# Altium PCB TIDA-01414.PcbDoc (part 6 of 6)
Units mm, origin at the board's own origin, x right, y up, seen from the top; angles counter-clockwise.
Board outline 400 x 135 mm, 4 copper layers (Top Copper, Copper Layer 2, Copper Layer 3, Bottom Copper), stack 1.567 mm thick; 835 components, 519 nets, 2420 pads, 2045 vias.
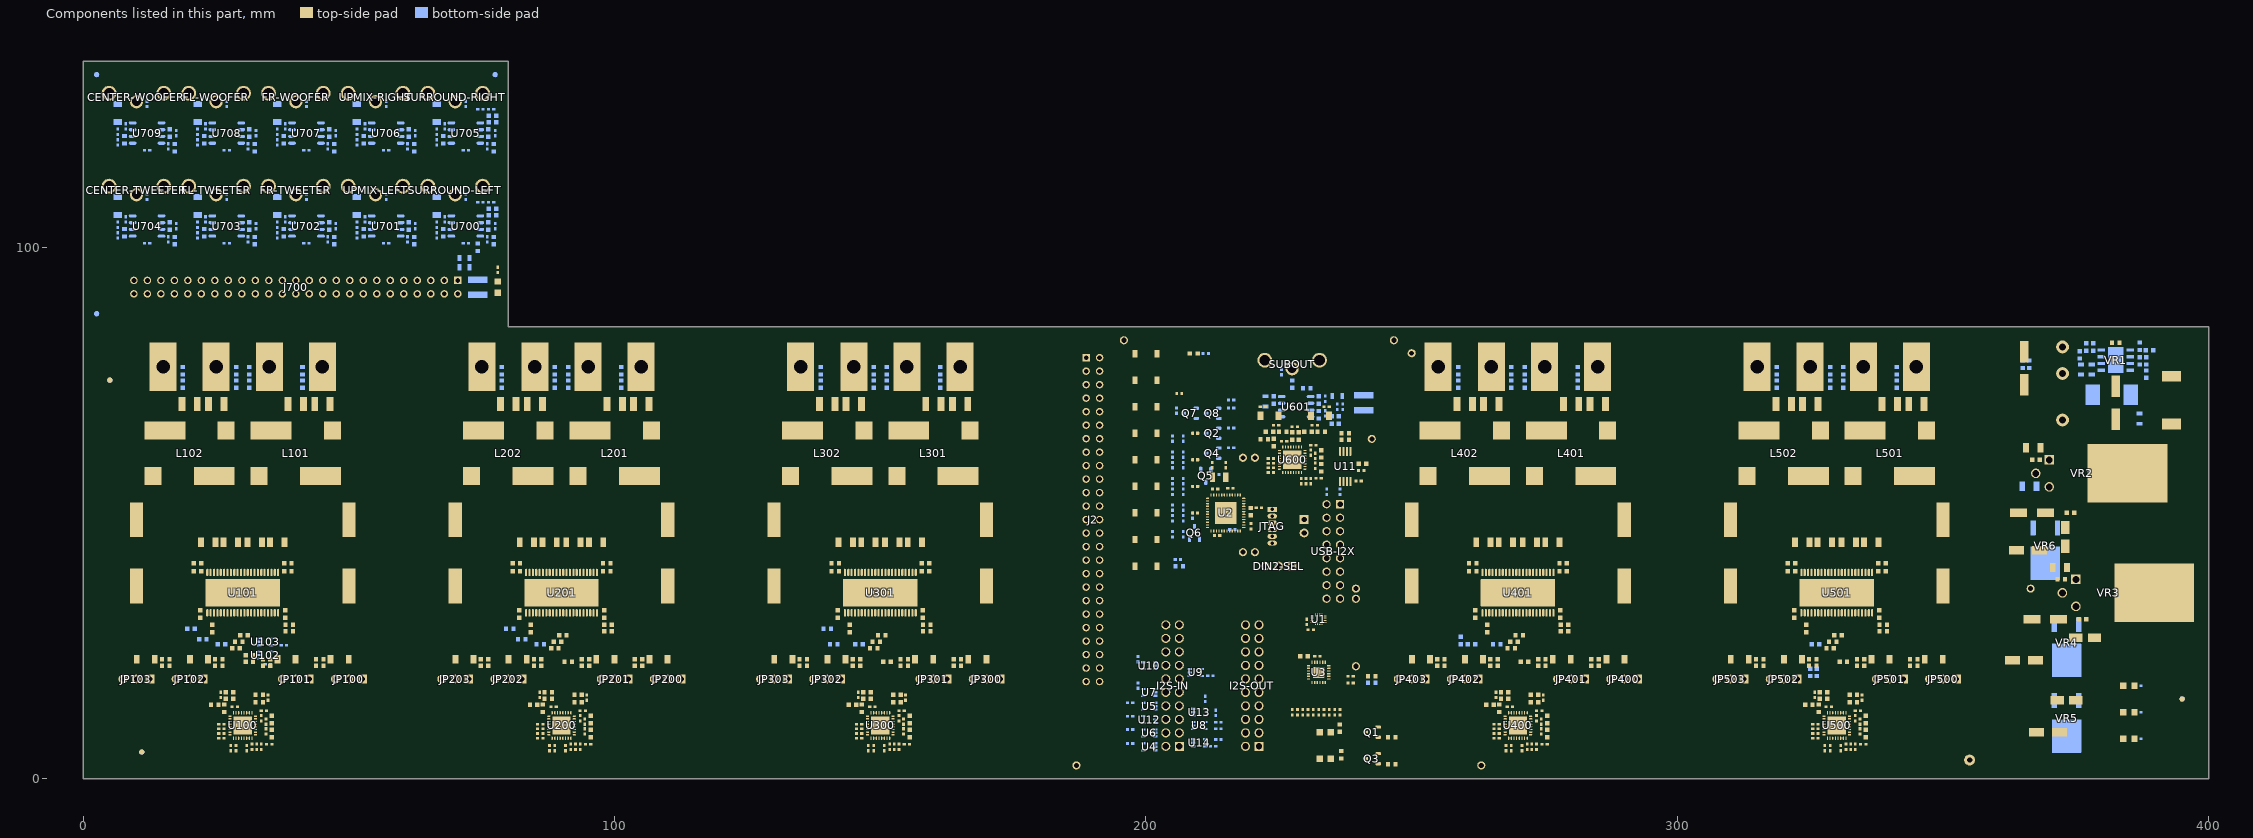
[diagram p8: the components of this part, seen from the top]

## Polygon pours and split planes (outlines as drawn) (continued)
15V on Bottom Copper "15V Bottom Copper" (solid, remove dead copper, pour order 561): 388.5,67.25 388.75,67 388.75,66.5 388.5,66.25 385.5,66.25 385.25,66.5 385.25,67 385.5,67.25 388.5,67.25
SW-VR1 on Bottom Copper "SW-VR1 Bottom Copper" (solid, remove dead copper, pour order 549): 383.75,70.25 383.75,74.75 384.5,75.5 384.5,77.25 386,77.25 386,76 387,75 387,70.25
PVDD on Bottom Copper "PWR-IN Bottom Copper" (solid, remove dead copper, pour order 547): 18 vertices, not listed, extent 362,77.5 380.5,82.5
OUT3D on Bottom Copper "OUT3D Bottom Copper" (solid, remove dead copper, pour order 525): 131.5,54.75 131.75,55 135.25,55 135.5,54.75 135.5,51.75 144,43.25 146,43.25 146.75,42.5 146.75,39.75 146.5,39.5 143,39.5 131.5,51
OUT3C on Bottom Copper "OUT3C Bottom Copper" (solid, remove dead copper, pour order 524): 149.25,40.5 148.75,40.5 147.75,41.5 147.75,44.25 144.5,47.5 144.5,54.75 144.75,55 148.25,55 148.5,54.75 148.5,47.25 149.5,46.25 149.5,40.75
OUT3B on Bottom Copper "OUT3B Bottom Copper" (solid, remove dead copper, pour order 523): 150.75,40.5 151.25,40.5 152.25,41.5 152.25,44.25 155.5,47.5 155.5,54.75 155.25,55 151.75,55 151.5,54.75 151.5,47.25 150.5,46.25 150.5,40.75
OUT3A on Bottom Copper "OUT3A Bottom Copper" (solid, remove dead copper, pour order 522): 164.75,54.75 164.5,55 161,55 160.75,54.75 160.75,48 156,43.25 154,43.25 153.25,42.5 153.25,39.75 153.5,39.5 157,39.5 164.75,47.25
OUT2D on Bottom Copper "OUT2D Bottom Copper" (solid, remove dead copper, pour order 521): 71.5,54.75 71.75,55 75.25,55 75.5,54.75 75.5,51.75 84,43.25 86,43.25 86.75,42.5 86.75,39.75 86.5,39.5 83,39.5 71.5,51
OUT2C on Bottom Copper "OUT2C Bottom Copper" (solid, remove dead copper, pour order 520): 89.25,40.5 88.75,40.5 87.75,41.5 87.75,44.25 84.5,47.5 84.5,54.75 84.75,55 88.25,55 88.5,54.75 88.5,47.25 89.5,46.25 89.5,40.75
OUT2B on Bottom Copper "OUT2B Bottom Copper" (solid, remove dead copper, pour order 519): 90.75,40.5 91.25,40.5 92.25,41.5 92.25,44.25 95.5,47.5 95.5,54.75 95.25,55 91.75,55 91.5,54.75 91.5,47.25 90.5,46.25 90.5,40.75
OUT2A on Bottom Copper "OUT2A Bottom Copper" (solid, remove dead copper, pour order 518): 104.75,54.75 104.5,55 101,55 100.75,54.75 100.75,48 96,43.25 94,43.25 93.25,42.5 93.25,39.75 93.5,39.5 97,39.5 104.75,47.25
OUT5A on Bottom Copper "OUT5A Bottom Copper" (solid, remove dead copper, pour order 517): 344.75,54.75 344.5,55 341,55 340.75,54.75 340.75,48 336,43.25 334,43.25 333.25,42.5 333.25,39.75 333.5,39.5 337,39.5 344.75,47.25
OUT5B on Bottom Copper "OUT5B Bottom Copper" (solid, remove dead copper, pour order 516): 330.75,40.5 331.25,40.5 332.25,41.5 332.25,44.25 335.5,47.5 335.5,54.75 335.25,55 331.75,55 331.5,54.75 331.5,47.25 330.5,46.25 330.5,40.75
OUT5C on Bottom Copper "OUT5C Bottom Copper" (solid, remove dead copper, pour order 515): 329.25,40.5 328.75,40.5 327.75,41.5 327.75,44.25 324.5,47.5 324.5,54.75 324.75,55 328.25,55 328.5,54.75 328.5,47.25 329.5,46.25 329.5,40.75
OUT5D on Bottom Copper "OUT5D Bottom Copper" (solid, remove dead copper, pour order 514): 311.5,54.75 311.75,55 315.25,55 315.5,54.75 315.5,51.75 324,43.25 326,43.25 326.75,42.5 326.75,39.75 326.5,39.5 323,39.5 311.5,51
OUT4A on Bottom Copper "OUT4A Bottom Copper" (solid, remove dead copper, pour order 499): 284.75,54.75 284.5,55 281,55 280.75,54.75 280.75,48 276,43.25 274,43.25 273.25,42.5 273.25,39.75 273.5,39.5 277,39.5 284.75,47.25
OUT4B on Bottom Copper "OUT4B Bottom Copper" (solid, remove dead copper, pour order 498): 270.75,40.5 271.25,40.5 272.25,41.5 272.25,44.25 275.5,47.5 275.5,54.75 275.25,55 271.75,55 271.5,54.75 271.5,47.25 270.5,46.25 270.5,40.75
OUT4C on Bottom Copper "OUT4C Bottom Copper" (solid, remove dead copper, pour order 497): 269.25,40.5 268.75,40.5 267.75,41.5 267.75,44.25 264.5,47.5 264.5,54.75 264.75,55 268.25,55 268.5,54.75 268.5,47.25 269.5,46.25 269.5,40.75
OUT4D on Bottom Copper "OUT4D Bottom Copper" (solid, remove dead copper, pour order 496): 251.5,54.75 251.75,55 255.25,55 255.5,54.75 255.5,51.75 264,43.25 266,43.25 266.75,42.5 266.75,39.75 266.5,39.5 263,39.5 251.5,51
OUT1A on Bottom Copper "OUT1A Bottom Copper" (solid, remove dead copper, pour order 453): 44.75,54.75 44.5,55 41,55 40.75,54.75 40.75,48 36,43.25 34,43.25 33.25,42.5 33.25,39.75 33.5,39.5 37,39.5 44.75,47.25
OUT1B on Bottom Copper "OUT1B Bottom Copper" (solid, remove dead copper, pour order 452): 30.75,40.5 31.25,40.5 32.25,41.5 32.25,44.25 35.5,47.5 35.5,54.75 35.25,55 31.75,55 31.5,54.75 31.5,47.25 30.5,46.25 30.5,40.75
OUT1C on Bottom Copper "OUT1C Bottom Copper" (solid, remove dead copper, pour order 451): 29.25,40.5 28.75,40.5 27.75,41.5 27.75,44.25 24.5,47.5 24.5,54.75 24.75,55 28.25,55 28.5,54.75 28.5,47.25 29.5,46.25 29.5,40.75
OUT1D on Bottom Copper "OUT1D Bottom Copper" (solid, remove dead copper, pour order 450): 11.5,54.75 11.75,55 15.25,55 15.5,54.75 15.5,51.75 24,43.25 26,43.25 26.75,42.5 26.75,39.75 26.5,39.5 23,39.5 11.5,51
GND-IO on Bottom Copper "GND-IO Bottom Copper" (solid, remove dead copper, pour order 543): 6,86 1,91 1,129 6,134 74,134 79.5,128.5 79.5,90.5 75,86
12V-OA-IO on Bottom Copper "12V-OA-IO Top Copper" (solid, remove dead copper, pour order 538): 72.25,93.25 72.25,98.75 73.25,99.75 75,99.75 76.25,98.5 76.25,93.25
12V-IO on Bottom Copper "12V-IO Bottom Copper" (solid, remove dead copper, pour order 540): 76.25,90.25 67.75,90.25 67,91 67,91.5 67.75,92.25 76.25,92.25 76.25,90.25
12V on Bottom Copper "12V Bottom Copper" (solid, remove dead copper, pour order 567): 365.5,56 362.75,56 362.25,55.5 362.25,54.5 362.75,54 365.5,54
GND on Bottom Copper "GND Bottom Copper" (solid, remove dead copper, pour order 617): 21 vertices, not listed, extent 0.5,0.5 399.5,84.5
3.3V-3 on Copper Layer 3 "3.3V-3 Copper Layer 3" (solid, remove dead copper, pour order 603): 19 vertices, not listed, extent 197.25,4.25 240.75,24.75
3.3V-1 on Copper Layer 3 "3.3V-1 Copper Layer 3" (solid, remove dead copper, pour order 591): 367.25,24 367.5,24.25 369.75,24.25 370,24.25 370.25,24 370.25,20.5 370,20.25 367.5,20.25 367.25,20.5
12V-OA-IO on Copper Layer 3 "12V-OA-IO Copper Layer 3" (solid, remove dead copper, pour order 539): 5,86 1,90 1,130 5,134 75,134 79.5,129.5 79.5,90.5 75,86
12V on Copper Layer 3 "12V Copper Layer 3" (solid, remove dead copper, pour order 537): 30 vertices, not listed, extent 22.5,26.25 364.25,56
PVDD on Copper Layer 3 "PVDD Copper Layer 3" (solid, remove dead copper, pour order 526): 21 vertices, not listed, extent 7,56 374,82.5
PVDD on Copper Layer 3 "PVDD Copper Layer 3" (solid, remove dead copper, pour order 527): 7,45 7,58 10,58 10,46 9,45
PVDD on Copper Layer 3 "PVDD Copper Layer 3" (solid, remove dead copper, pour order 528): 51,45 50,46 50,58 53,58 53,45
PVDD on Copper Layer 3 "PVDD Copper Layer 3" (solid, remove dead copper, pour order 529): 111,45 110,46 110,58 113,58 113,45
PVDD on Copper Layer 3 "PVDD Copper Layer 3" (solid, remove dead copper, pour order 530): 67,45 67,58 70,58 70,46 69,45
PVDD on Copper Layer 3 "PVDD Copper Layer 3" (solid, remove dead copper, pour order 531): 171,45 170,46 170,58 173,58 173,45
PVDD on Copper Layer 3 "PVDD Copper Layer 3" (solid, remove dead copper, pour order 532): 127,45 127,58 130,58 130,46 129,45
PVDD on Copper Layer 3 "PVDD Copper Layer 3" (solid, remove dead copper, pour order 533): 291,45 290,46 290,58 293,58 293,45
PVDD on Copper Layer 3 "PVDD Copper Layer 3" (solid, remove dead copper, pour order 534): 247,45 247,58 250,58 250,46 249,45
PVDD on Copper Layer 3 "PVDD Copper Layer 3" (solid, remove dead copper, pour order 535): 351,45 350,46 350,59.5 353,59.5 353,45
PVDD on Copper Layer 3 "PVDD Copper Layer 3" (solid, remove dead copper, pour order 536): 307,45 307,58 310,58 310,46 309,45
3.3V-4 on Copper Layer 3 "3.3V-1 Copper Layer 3" (solid, remove dead copper, pour order 563): 21.5,13 22.75,14.25 153.5,14.25 158.25,9.5 158.25,8.875 154.5,5.125 33.875,5.125 31.875,7.125 23.875,7.125 21.5,9.5
3.3V-2 on Copper Layer 3 "3.3V-2 Copper Layer 3" (solid, pour order 565): 262.5,13.875 262.875,14.25 330.75,14.25 333.75,11.25 370,11.25 370.25,11 370.25,5.5 369.75,5 266.5,5 262.5,9
15V on Copper Layer 3 "15V Copper Layer 3" (solid, remove dead copper, pour order 573): 29 vertices, not listed, extent 369,36.25 394.75,69.75
3.3V on Copper Layer 3 "3.3V Copper Layer 3" (solid, remove dead copper, pour order 605): 206.625,67.125 205,65.5 205,42.5 211.25,36.25 226.75,36.25 230,33 240,33 242,35 242,58 235,65 224.25,65 222.125,67.125
GND on Copper Layer 3 "GND Copper Layer 3" (solid, remove dead copper, pour order 613): 21 vertices, not listed, extent 0.5,0.5 399.5,84.5
GND-IO on Copper Layer 2 "GND-IO Copper Layer 2" (solid, remove dead copper, pour order 542): 5,86 1,90 1,130 5,134 75,134 79.5,129.5 79.5,90.5 75,86
GND on Copper Layer 2 "GND Copper Layer 2" (solid, remove dead copper, pour order 615): 21 vertices, not listed, extent 0.5,0.5 399.5,84.5

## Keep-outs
Keep-Out Layer:
  lines w0.2: -0.5,-0.5 400.5,-0.5 400.5,85.5 80.5,85.5 80.5,135.5 -0.5,135.5 -0.5,-0.5

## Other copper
Top Copper:
  text ".Layer_Name" at 14.656,-21.806 h1.52
Copper Layer 2:
  text ".Layer_Name" at 14.656,-21.806 h1.52
Copper Layer 3:
  text ".Layer_Name" at 14.656,-21.806 h1.52
Bottom Copper:
  text ".Layer_Name" at 14.656,-21.806 h1.52

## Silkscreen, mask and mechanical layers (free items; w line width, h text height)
Top SilkScreen:
  circle w0.254: c120,11.25 r0.75
  circle w0.254: c117.5,11.25 r0.75
  circle w0.254: c297.5,11.25 r0.75
  circle w0.254: c300,11.25 r0.75
  rectangle: 376.25,37.25 380.5,37.75
  rectangle: 373.75,34.75 380.5,35.25
  rectangle: 376.25,32.25 380.5,32.75
  rectangle: 371.25,54.75 375.5,55.25
  rectangle: 368.75,57.25 375.5,57.75
  rectangle: 371.25,59.75 375.5,60.25
  lines w0.1: 375.5,51.75 392.5,51.75 392.5,63.25 375.5,63.25 375.5,51.75 ; 380.5,29.25 380.5,40.75 397.5,40.75 397.5,29.25 380.5,29.25
  lines w0.2: 19.6,69.725 20.4,69.725 ; 19.6,71.275 20.4,71.275 ; 24.6,69.725 25.4,69.725 ; 24.6,71.275 25.4,71.275 ; 39.6,69.725 40.4,69.725 ; 39.6,71.275 40.4,71.275 ; 44.6,69.725 45.4,69.725 ; 44.6,71.275 45.4,71.275 ; 60,11.25 60,74 ; 79.6,69.725 80.4,69.725 ; 79.6,71.275 80.4,71.275 ; 84.6,69.725 85.4,69.725 ; 84.6,71.275 85.4,71.275 ; 99.6,69.725 100.4,69.725 ; 99.6,71.275 100.4,71.275 ; 104.6,69.725 105.4,69.725 ; 104.6,71.275 105.4,71.275 ; 120,15.5 120,66 ; 139.6,69.725 140.4,69.725 ; 139.6,71.275 140.4,71.275 ; 144.6,69.725 145.4,69.725 ; 144.6,71.275 145.4,71.275 ; 159.6,69.725 160.4,69.725 ; 159.6,71.275 160.4,71.275 ; 164.6,69.725 165.4,69.725 ; 164.6,71.275 165.4,71.275 ; 180,5 180,85 ; 237.75,32 237.75,25.25 239.25,25.25 ; 237.75,53.5 237.75,54.5 ; 239.25,0 239.25,3.5 ; 239.25,5.5 239.25,8.5 ; 239.25,10.5 239.25,16 ; 239.25,22.25 239.25,32.5 ; 239.25,37 239.25,54.5 ; 259.6,69.725 260.4,69.725 ; 259.6,71.275 260.4,71.275 ; 264.6,69.725 265.4,69.725 ; 264.6,71.275 265.4,71.275 ; 279.6,69.725 280.4,69.725 ; 279.6,71.275 280.4,71.275 ; 284.6,69.725 285.4,69.725 ; 284.6,71.275 285.4,71.275 ; 300,15.5 300,66 ; 319.6,69.725 320.4,69.725 ; 319.6,71.275 320.4,71.275 ; 324.6,69.725 325.4,69.725 ; 324.6,71.275 325.4,71.275 ; 325.125,6.5 325.625,7.125 ; 339.6,69.725 340.4,69.725 ; 339.6,71.275 340.4,71.275 ; 344.6,69.725 345.4,69.725 ; 344.6,71.275 345.4,71.275 ; 360,0 360,85 ; 116,10 116,12.5 124,12.5 124,10 116,10 ; 121.75,10.5 123.25,10.5 123.25,12 121.75,12 121.75,10.5 ; 296,10 304,10 304,12.5 296,12.5 296,10 ; 301.75,10.5 301.75,12 303.25,12 303.25,10.5 301.75,10.5
  text "ANALOG / INPUT / BOARD" at 65.5,98.75 h1.5
  text "Sound Bar TPA3244" at 28.5,98.5 h1.5
  text "VMAX=30V" at 369,83 h1.5
  text "SUBWOOFER" at 236.25,72 h1.5 r90
  text "1" at 225.5,50 h1.5
  text "AD0" at 220.5,36.75 h1.5
  text "AD1" at 226,36.75 h1.5
  text "ANALOG INPUT BOARD" at 185.5,34.25 h1.5 r90
  text "INPUT SELECTS" at 112.25,13.25 h1.5
  text "INPUT SELECTS" at 292.25,13.25 h1.5
  text "EXT" at 115.5,8 h1.5
  text "DAC" at 120.75,8 h1.5
  text "EXT" at 295.5,8 h1.5
  text "DAC" at 300.75,8 h1.5
  text "TPA3244 Dolby Atmos" at 45,7 h2
  text "SoundBar Reference Design" at 42.25,4 h2
  text "TIDA-01414" at 51.75,1.25 h1.75
  text "SURROUND" at 25,0.625 h1.5
  text "UP MIX" at 86.25,0.625 h1.5
  text "FRONT RIGHT" at 143.5,0.625 h1.5
  text "FRONT LEFT" at 264.25,0.625 h1.5
  text "CENTER" at 326.25,0.625 h1.5
  text ".Layer_Name" at 14.656,-21.806 h1.52
Bottom Silk:
  lines w0.1: 76.875,102.875 78.75,102.5 ; 76.875,120.375 78.75,120 ; 387.55,79.875 387.675,79.975 388.975,79.975 389.725,79.5
  text ".Layer_Name" at 14.656,-21.806 h1.52
Top Paste:
  text ".Layer_Name" at 14.656,-21.806 h1.52
Bottom Paste:
  text ".Layer_Name" at 14.656,-21.806 h1.52
Top SolderMask:
  text ".Layer_Name" at 14.656,-21.806 h1.52
Bottom SolderMask:
  text ".Layer_Name" at 14.656,-21.806 h1.52
Drill Guide:
  text ".Layer_Name" at 230.25,143.75 h1.52
M1 Board Outline:
  lines w0.2: 50,85 52.5,75 67.5,75 70,85 ; 110,85 112.5,75 127.5,75 130,85 ; 290,85 292.5,75 307.5,75 310,85
  lines w0.25: 0,85 400,85 400,0 0,0 0,135 80,135 80,85
  text ".Layer_Name" at 58,-22 h1.52
M2 Board Dimensions:
  text ".Layer_Name" at 84,-22 h1.52
M3 3D STEP Top:
  text ".Layer_Name" at 14.656,-21.806 h1.52
M4 3D STEP Bottom:
  text ".Layer_Name" at 14.656,-21.806 h1.52
M5 Assembly Top:
  lines w0.254: -7.417,-23.626 160.223,-23.626 ; -7.417,-18.462 160.274,-18.462 ; -7.417,-13.297 -7.417,-28.791 94.31,-28.791 160.274,-28.791 160.274,-13.297 -7.404,-13.297 -7.404,-28.791 32.614,-28.791 ; 55.194,-28.791 55.194,-13.297 ; 87.376,-18.462 87.376,-13.297 ; 108.712,-18.462 108.712,-13.297 ; 124.511,-28.956 124.511,-23.804
  text "COMPONENTS MARKED 'DNP' SHOULD NOT BE POPULATED." at 29.299,-8.09 h1.52
  text "ASSEMBLY VARIANT:" at 29.286,-11.024 h1.52
  text ".VariantName" at 55.601,-11.024 h1.52
  text "PCB VIEWED FROM TOP SIDE" at -5.804,-16.654 h1.52
  text "BOARD #:" at 57.099,-16.654 h1.52
  text ".PRJ_Number" at 70.955,-16.654 h1.52
  text "REV:" at 92.405,-16.654 h1.52
  text ".PCB_Rev" at 99.809,-16.654 h1.52
  text "SVN REV:" at 113.69,-16.654 h1.52
  text ".VersionControl_RevNumber" at 126.543,-16.654 h1.52
  text "TID #:" at 57.099,-21.819 h1.52
  text ".TID" at 70.955,-21.819 h1.52
  text "PLOT NAME =" at -5.804,-27.034 h1.52
  text ".plot_File_Name" at 14.656,-27.034 h1.52
  text "GENERATED    :" at 57.15,-27.034 h1.52
  text ".Print_Date" at 79.235,-27.034 h1.52
  text ".Print_Time" at 97.752,-27.034 h1.52
  text "TEXAS INSTRUMENTS" at 129.87,-27.034 h1.52
M6 Assembly Bottom:
  lines w0.254: -7.429,-18.474 160.261,-18.474 ; -7.379,-23.639 160.261,-23.639 ; 28.334,-28.969 28.334,-23.817 ; 44.133,-18.474 44.133,-13.31 ; 65.468,-18.474 65.468,-13.31 ; 97.65,-28.804 97.65,-13.31 ; 120.231,-28.804 160.249,-28.804 160.249,-13.31 -7.429,-13.31 -7.429,-28.804 58.534,-28.804 160.261,-28.804 160.261,-13.31
  text "COMPONENTS MARKED 'DNP' SHOULD NOT BE POPULATED." at 154.991,-8.077 h1.52
  text ".VariantName" at 128.473,-11.024 h1.52
  text "ASSEMBLY VARIANT:" at 154.864,-11.024 h1.52
  text ".VersionControl_RevNumber" at 26.302,-16.667 h1.52
  text "SVN REV:" at 39.154,-16.667 h1.52
  text ".PCB_Rev" at 53.035,-16.667 h1.52
  text "REV:" at 60.439,-16.667 h1.52
  text ".PRJ_Number" at 81.89,-16.667 h1.52
  text "BOARD #:" at 95.745,-16.667 h1.52
  text "PCB VIEWED FROM BOTTOM SIDE" at 158.648,-16.667 h1.52
  text ".TID" at 81.89,-21.831 h1.52
  text "TID #:" at 95.745,-21.831 h1.52
  text "TEXAS INSTRUMENTS" at 22.974,-27.047 h1.52
  text ".Print_Time" at 55.093,-27.047 h1.52
  text ".Print_Date" at 73.609,-27.047 h1.52
  text "GENERATED    :" at 95.694,-27.047 h1.52
  text ".plot_File_Name" at 138.189,-27.047 h1.52
  text "PLOT NAME =" at 158.648,-27.047 h1.52
M9 Title Sheet:
  drawing of 59 lines, arcs and shapes, not listed
  text "PROJECT TITLE:" at 340.793,186.952 h1.14
  text ".PRJ_Title" at 342.063,183.565 h1.78
  text "DESIGNED FOR:" at 340.793,179.306 h1.14
  text ".PRJ_Customer" at 342.063,175.75 h1.78
  text "FILE NAME:" at 340.793,171.686 h1.14
  text ".PCB_File_Name_No_Path" at 342.063,168.638 h1.78
  text "Texas Instruments (TI) and/or its licensors do not warrant the accuracy or completeness of this specification" at 212.827,-15.376 h1.14
  text "ENGINEER:" at 339.052,-15.583 h1.14
  text "LAYOUT BY:" at 377.279,-15.583 h1.14
  text "or any information contained therein. TI and/or its licensors do not warrant that this design will meet" at 211.684,-18.237 h1.14
  text ".PRJ_Engineer" at 340.322,-19.52 h1.78
  text ".PCB_Layout" at 378.562,-19.52 h1.78
  text "the specifications, will be suitable for your application or fit for any particular purpose, or will operate in" at 211.684,-21.099 h1.14
  text "ALTIUM DESIGNER VERSION:" at 377.279,-23.457 h1.14
  text "an implementation. TI and/or its licensors do not warrant that the design is production worthy. You should" at 211.684,-23.961 h1.14
  text "completely validate and test your design implementation to confirm the system functionality for your application." at 212.827,-26.822 h1.14
  text ".print_Scale" at 340.322,-26.843 h1.78
  text ".Application_BuildNumber" at 378.562,-26.843 h1.78
M10 Fab Notes:
  drawing of 187 lines, arcs and shapes, not listed
  text ".Layer_Name" at 306.5,199 h1.52
  text "MATERIAL:" at 72.398,198.326 h1.52
  text "DESIGN INFORMATION" at 21.562,198.159 h1.52
  text "DRILLING:" at 149.868,197.972 h1.52
  text "IMMERSION GOLD (ENIG)" at 256.32,196.786 h1.52
  text "ENEPIG" at 290.293,196.702 h1.52
  text "SURFACE FINISH:" at 229.37,196.677 h1.52
  text "X" at 251.571,196.677 h1.52
  text "REFERENCE:" at 151.767,195.001 h1.52
  text "X" at 168.232,195.001 h1.52
  text "AS SHOWN" at 172.982,195.001 h1.52
  text "X" at 191.118,195.001 h1.52
  text "NC_DRILL FILES" at 194.598,195.001 h1.52
  text "FR-4 High Tg" at 97.454,194.761 h1.52
  text "FR-408" at 83.092,194.543 h1.52
  text "OTHER" at 120.887,194.543 h1.52
  text "X" at 93.519,194.451 h1.52
  text "MIN. TRACK WIDTH:" at 5.19,193.587 h1.52
  text "8" at 33.034,193.587 h1.52
  text "MIL" at 36.965,193.587 h1.52
  text "IMM. TIN/SILVER OR EQUIV" at 237.741,192.689 h1.52
  text "OTHER" at 274.1,192.689 h1.52
  text "PTH COPPER THICKNESS:" at 151.767,190.987 h1.52
  text "X" at 180.475,190.987 h1.52
  text "20-30 um" at 183.955,190.987 h1.52
  text "OTHER" at 202.167,190.987 h1.52
  text "62 MIL (1.6mm) +/-10%" at 91.222,190.41 h1.52
  text "THICKNESS:" at 74.297,190.302 h1.52
  text "X" at 87.967,190.302 h1.52
  text "OTHER" at 123.859,190.302 h1.52
  text "MIN. CLEARANCE:" at 5.19,190.235 h1.52
  text "0.2" at 31.51,190.235 h1.52
  text "mm" at 36.965,190.235 h1.52
  text "ARRAY/PANEL:" at 229.37,188.143 h1.52
  text "CUT AND TRIM PER M1 BOARD OUTLINE" at 256.32,188.034 h1.52
  text "BOARD FINISH:" at 149.868,186.949 h1.52
  text "MIN. VIA PAD SIZE:" at 5.19,186.882 h1.52
  text "20" at 32.273,186.882 h1.52
  text "MIL" at 36.965,186.882 h1.52
  text "TOLERANCE:" at 74.297,186.288 h1.52
  text "X" at 95.616,186.288 h1.52
  text "ANSI IPC-6012 TYPE 3 CLASS 2" at 100.364,186.288 h1.52
  text "N.C. ROUTE" at 256.32,184.18 h1.52
  text "X" at 273.566,184.18 h1.52
  text "V. SCORE" at 278.316,184.18 h1.52
  text "SILKSCREEN:" at 153.811,183.952 h1.52
  text "X" at 177.91,183.952 h1.52
  text "TOP" at 181.11,183.952 h1.52
  text "X" at 190.864,183.952 h1.52
  text "BOTTOM" at 194.09,183.952 h1.52
  text "0.05mm (2MIL)" at 22.843,183.282 h1.52
  text "MINIMUM ANNULAR RING" at -3.173,183.174 h1.52
  text "EXTERNAL" at 40.826,183.174 h1.52
  text "OTHER +/-" at 100.364,182.326 h1.52
  text "PER" at 1.907,180.176 h1.52
  text "IPC-D-275 CLASS 2 LEVEL C" at 7.495,180.176 h1.52
  text "SILKSCREEN COLOR:" at 153.811,179.71 h1.52
  text "X" at 177.883,179.71 h1.52
  text "WHITE" at 181.11,179.71 h1.52
  text "OTHER" at 194.09,179.71 h1.52
  text "CERTIFICATION:" at 229.624,178.668 h1.52
  text "MATERIALS AND WORKMANSHIP FOR ALL PCBS" at 248.039,178.668 h1.52
  text "BOW & TWIST:" at 74.297,178.338 h1.52
  text "X" at 95.616,178.338 h1.52
  text "ANSI IPC-6012 TYPE 3 CLASS 2" at 100.364,178.338 h1.52
  text "+/-" at 35.328,177.306 h1.52
  text "MIL, HOLES" at 45.296,177.324 h1.52
  text "+/-" at 57.02,177.306 h1.52
  text "REGISTRATION TOLERANCES:" at -3.173,177.179 h1.52
  text "METAL" at 27.302,177.179 h1.52
  text "5" at 41.937,177.179 h1.52
  text "3" at 63.095,177.179 h1.52
  text "MIL" at 66.048,177.179 h1.52
  text "TO MEET OR EXCEED THE REQUIREMENTS OF:" at 248.039,176.179 h1.52
  text "X" at 181.211,175.666 h1.52
  text "BLUE" at 184.438,175.666 h1.52
  text "OTHER" at 200.135,175.666 h1.52
  text "SOLDER RESIST COLOR:" at 153.811,175.392 h1.52
  text "+/-" at 57.02,174.309 h1.52
  text "OTHER +/-" at 100.364,174.312 h1.52
  text "HOLE SIZE TOLERANCE (UNLESS OTHERWISE SPECIFIED):" at -3.173,174.182 h1.52
  text "3" at 63.095,174.182 h1.52
  text "MIL" at 66.048,174.182 h1.52
  text "X" at 238.552,172.712 h1.52
  text "ANSI IPC-A-600F CLASS ->" at 242.083,172.712 h1.52
  text "X" at 283.715,172.712 h1.52
  text "2" at 286.736,172.712 h1.52
  text "1" at 278.735,172.674 h1.52
  text "3" at 295.728,172.674 h1.52
  text "X" at 181.211,171.348 h1.52
  text "MATTE" at 184.438,171.348 h1.52
  text "SEMI-GLOSS" at 200.123,171.332 h1.52
  text "SPECIAL NOTES" at 24.638,168.656 h1.52
  text "X" at 259.229,168.661 h1.52
  text "RoHS" at 262.708,168.661 h1.52
  text "OTHER" at 279.076,168.661 h1.52
  text "PER ORDER" at 289.161,168.661 h1.52
  text "1. SCORE BOARD WHERE INDICATED FOR SEPARATION AFTER ASSEMBLY" at -4.064,164.592 h1.52
  text "ALL BOARDS MUST MEET OR EXCEED UL94-V0 REQUIREMENTS." at 230.324,164.454 h1.52
  text "2. CUT OUT 3 AREAS OF BOARD WHERE INDICATED." at -4.064,162.56 h1.52
  text "PCB MUST BEAR THE UL94V-0 UL REGISTERED MATERIAL ID NUMBER" at 230.324,161.406 h1.52
  text "ADDITIONAL REQUIREMENTS:" at 229.624,157.002 h1.52
  text "MICROSECTION:" at 231.523,154.081 h1.52
  text "YES" at 254.529,154.081 h1.52
  text "REQUIRED" at 276.411,150.115 h1.52
  text "BARE BOARD ELEC. TEST:" at 231.523,150.043 h1.52
  text "NONE" at 264.689,150.043 h1.52
  text "X" at 273.185,150.043 h1.52
  text "PER ORDER" at 291.448,150.043 h1.52
  text "SCORE LINE" at 84.25,88.5 h1.5
  text "CUT OUT" at 55.5,79.5 h1.5
  text "CUT OUT" at 115.5,79.5 h1.5
  text "CUT OUT" at 295.5,79.5 h1.5
M11 Gerber Information:
  lines w0.254: -7.417,-23.626 160.223,-23.626 ; -7.417,-18.462 160.274,-18.462 ; -7.417,-13.297 -7.417,-28.791 94.31,-28.791 160.274,-28.791 160.274,-13.297 -7.404,-13.297 -7.404,-28.791 32.614,-28.791 ; 55.194,-28.791 55.194,-13.297 ; 87.376,-18.462 87.376,-13.297 ; 108.712,-18.462 108.712,-13.297 ; 124.511,-28.956 124.511,-23.804
  text "ALL ARTWORK VIEWED FROM TOP SIDE" at -5.804,-16.654 h1.52
  text "BOARD #:" at 57.099,-16.654 h1.52
  text ".PRJ_Number" at 70.955,-16.654 h1.52
  text "REV:" at 92.405,-16.654 h1.52
  text ".PCB_Rev" at 99.809,-16.654 h1.52
  text "SVN REV:" at 113.69,-16.654 h1.52
  text ".VersionControl_RevNumber" at 126.543,-16.654 h1.52
  text "LAYER NAME =" at -5.804,-21.806 h1.52
  text "PLOT NAME =" at -5.804,-27.034 h1.52
  text ".plot_File_Name" at 14.656,-27.034 h1.52
  text "GENERATED    :" at 57.15,-27.034 h1.52
  text ".Print_Date" at 79.235,-27.034 h1.52
  text ".Print_Time" at 97.752,-27.034 h1.52
  text "TEXAS INSTRUMENTS" at 129.87,-27.034 h1.52
M12 Stackup:
  drawing of 295 lines, arcs and shapes, not listed
  text ".Layer_Name" at 85,133 h1.52
  text "Layer" at 86.715,129.481 h1.52
  text "Name" at 97.126,129.481 h1.52
  text "Material" at 125.058,129.481 h1.52
  text "Thickness" at 146.896,129.481 h1.52
  text "Constant" at 163.402,129.481 h1.52
  text "Board Layer Stack" at 177.877,129.481 h1.52
  text "1" at 86.715,126.433 h1.52
  text "Top SilkScreen" at 97.126,126.433 h1.52
  text "2" at 86.715,123.385 h1.52
  text "Top SolderMask" at 97.126,123.385 h1.52
  text "Solder Resist" at 125.058,123.385 h1.52
  text "0.40mil" at 146.896,123.385 h1.52
  text "3.5" at 163.402,123.385 h1.52
  text "3" at 86.715,120.337 h1.52
  text "Top Copper" at 97.126,120.337 h1.52
  text "Copper" at 125.058,120.337 h1.52
  text "2.74mil" at 146.896,120.337 h1.52
  text "4" at 86.715,117.289 h1.52
  text "Dielectric 1" at 97.126,117.289 h1.52
  text "FR-4" at 125.058,117.289 h1.52
  text "8.00mil" at 146.896,117.289 h1.52
  text "4.2" at 163.402,117.289 h1.52
  text "5" at 86.715,114.241 h1.52
  text "Copper Layer 2" at 97.126,114.241 h1.52
  text "Copper" at 125.058,114.241 h1.52
  text "1.40mil" at 146.896,114.241 h1.52
  text "6" at 86.715,111.193 h1.52
  text "Dielectric 2" at 97.126,111.193 h1.52
  text "FR-4" at 125.058,111.193 h1.52
  text "37.42mil" at 146.896,111.193 h1.52
  text "4.2" at 163.402,111.193 h1.52
  text "7" at 86.715,108.145 h1.52
  text "Copper Layer 3" at 97.126,108.145 h1.52
  text "Copper" at 125.058,108.145 h1.52
  text "1.40mil" at 146.896,108.145 h1.52
  text "8" at 86.715,105.097 h1.52
  text "Dielectric 3" at 97.126,105.097 h1.52
  text "FR-4" at 125.058,105.097 h1.52
  text "8.00mil" at 146.896,105.097 h1.52
  text "4.2" at 163.402,105.097 h1.52
  text "9" at 86.715,102.049 h1.52
  text "Bottom Copper" at 97.126,102.049 h1.52
  text "Copper" at 125.058,102.049 h1.52
  text "2.74mil" at 146.896,102.049 h1.52
  text "10" at 86.715,99.001 h1.52
  text "Bottom SolderMask" at 97.126,99.001 h1.52
  text "Solder Resist" at 125.058,99.001 h1.52
  text "0.40mil" at 146.896,99.001 h1.52
  text "3.5" at 163.402,99.001 h1.52
  text "11" at 86.715,95.953 h1.52
  text "Bottom Silk" at 97.126,95.953 h1.52
M13 Component Bodies Top:
  text ".Layer_Name" at 14.656,-21.806 h1.52
M14 Component Bodies Bottom:
  text ".Layer_Name" at 14.656,-21.806 h1.52
M15 Courtyards Top:
  text ".Layer_Name" at 14.656,-21.806 h1.52
M16 Courtyards Bottom:
  text ".Layer_Name" at 14.656,-21.806 h1.52
Drill Drawing:
  lines w0.254: 231.426,96.426 232.832,96.426 232.832,97.831 231.426,97.831 231.426,96.426 ; 231.426,106.264 231.778,106.264 231.778,105.913 232.481,105.913 232.481,106.264 232.832,106.264 232.832,106.967 232.481,106.967 232.481,107.318 231.778,107.318 231.778,106.967 231.426,106.967 231.426,106.264 ; 231.426,109.075 231.426,109.426 231.778,109.778 231.426,110.129 231.426,110.48 231.778,110.48 232.129,110.129 232.481,110.48 232.832,110.48 232.832,110.129 232.481,109.778 232.832,109.426 232.832,109.075 232.481,109.075 232.129,109.426 231.778,109.075 231.426,109.075 ; 231.426,118.913 231.778,118.913 232.129,118.562 232.481,118.913 232.832,118.913 232.481,119.265 232.832,119.616 232.481,119.616 232.129,119.967 231.778,119.616 231.426,119.616 231.778,119.265 231.426,118.913 ; 231.426,121.724 232.129,122.075 232.832,121.724 232.481,122.427 232.832,123.13 232.129,122.778 231.426,123.13 231.778,122.427 231.426,121.724 ; 231.426,125.589 232.129,124.886 232.832,125.589 232.129,126.292 231.426,125.589 ; 231.426,131.211 232.832,131.211 232.832,132.616 231.426,132.616 231.426,131.211 ; 231.426,137.887 231.778,137.887 231.778,137.536 232.481,137.536 232.481,137.887 232.832,137.887 232.832,138.59 232.481,138.59 232.481,138.941 231.778,138.941 231.778,138.59 231.426,138.59 231.426,137.887 ; 231.708,106.405 231.918,106.405 231.918,106.194 232.34,106.194 232.34,106.405 232.551,106.405 232.551,106.826 232.34,106.826 232.34,107.037 231.918,107.037 231.918,106.826 231.708,106.826 231.708,106.405 ; 231.708,109.356 231.708,109.567 231.918,109.778 231.708,109.988 231.708,110.199 231.918,110.199 232.129,109.988 232.34,110.199 232.551,110.199 232.551,109.988 232.34,109.778 232.551,109.567 232.551,109.356 232.34,109.356 232.129,109.567 231.918,109.356 231.708,109.356 ; 231.708,122.005 232.129,122.216 232.551,122.005 232.34,122.427 232.551,122.848 232.129,122.638 231.708,122.848 231.918,122.427 231.708,122.005 ; 231.708,131.492 232.551,131.492 232.551,132.335 231.708,132.335 231.708,131.492
  lines w0.305: 230.152,92.315 314.522,92.315 ; 230.152,139.749 314.522,139.749 ; 238.738,89.152 238.738,142.911 ; 247.176,89.152 247.176,142.911 ; 263.342,89.152 263.342,142.911 ; 269.926,89.152 269.926,142.911 ; 279.457,89.152 279.457,142.911 ; 300.131,89.152 300.131,142.911 ; 230.152,89.152 314.522,89.152 314.522,142.911 230.152,142.911 230.152,89.152
  text "Symbol" at 232.05,140.698 h1.83
  text "Quantity" at 239.687,140.698 h1.83
  text "Finished Hole Size" at 248.124,140.698 h1.83
  text "Plated" at 264.291,140.698 h1.83
  text "Hole Type" at 270.875,140.698 h1.83
  text "Drill Layer Pair" at 280.406,140.698 h1.83
  text "Hole Tolerance" at 301.08,140.698 h1.83
  text "274" at 239.687,137.536 h1.52
  text "0.200mm (7.87mil)" at 248.124,137.536 h1.52
  text "PTH" at 264.291,137.536 h1.52
  text "Round" at 270.875,137.536 h1.52
  text "Top Copper - Bottom Copper" at 280.406,137.536 h1.52
  text "1762" at 239.687,134.373 h1.52
  text "0.254mm (10.00mil)" at 248.124,134.373 h1.52
  text "PTH" at 264.291,134.373 h1.52
  text "Round" at 270.875,134.373 h1.52
  text "Top Copper - Bottom Copper" at 280.406,134.373 h1.52
  text "C" at 231.407,134.12 h1.41
  text "6" at 239.687,131.211 h1.52
  text "0.660mm (26.00mil)" at 248.124,131.211 h1.52
  text "PTH" at 264.291,131.211 h1.52
  text "Round" at 270.875,131.211 h1.52
  text "Top Copper - Bottom Copper" at 280.406,131.211 h1.52
  text "100" at 239.687,128.049 h1.52
  text "0.890mm (35.04mil)" at 248.124,128.049 h1.52
  text "PTH" at 264.291,128.049 h1.52
  text "Round" at 270.875,128.049 h1.52
  text "Top Copper - Bottom Copper" at 280.406,128.049 h1.52
  text "D" at 231.407,127.795 h1.41
  text "6" at 239.687,124.886 h1.52
  text "0.940mm (37.00mil)" at 248.124,124.886 h1.52
  text "PTH" at 264.291,124.886 h1.52
  text "Round" at 270.875,124.886 h1.52
  text "Top Copper - Bottom Copper" at 280.406,124.886 h1.52
  text "8" at 239.687,121.724 h1.52
  text "0.965mm (38.00mil)" at 248.124,121.724 h1.52
  text "PTH" at 264.291,121.724 h1.52
  text "Round" at 270.875,121.724 h1.52
  text "Top Copper - Bottom Copper" at 280.406,121.724 h1.52
  text "66" at 239.687,118.562 h1.52
  text "1.016mm (40.00mil)" at 248.124,118.562 h1.52
  text "PTH" at 264.291,118.562 h1.52
  text "Round" at 270.875,118.562 h1.52
  text "Top Copper - Bottom Copper" at 280.406,118.562 h1.52
  text "16" at 239.687,115.399 h1.52
  text "1.020mm (40.16mil)" at 248.124,115.399 h1.52
  text "PTH" at 264.291,115.399 h1.52
  text "Round" at 270.875,115.399 h1.52
  text "Top Copper - Bottom Copper" at 280.406,115.399 h1.52
  text "+/-0.050mm" at 301.08,115.399 h1.52
  text "F" at 231.407,115.146 h1.41
  text "40" at 239.687,112.237 h1.52
  text "1.200mm (47.24mil)" at 248.124,112.237 h1.52
  text "PTH" at 264.291,112.237 h1.52
  text "Round" at 270.875,112.237 h1.52
  text "Top Copper - Bottom Copper" at 280.406,112.237 h1.52
  text "E" at 231.407,111.983 h1.41
  text "3" at 239.687,109.075 h1.52
  text "1.270mm (50.00mil)" at 248.124,109.075 h1.52
  text "PTH" at 264.291,109.075 h1.52
  text "Round" at 270.875,109.075 h1.52
  text "Top Copper - Bottom Copper" at 280.406,109.075 h1.52
  text "6" at 239.687,105.913 h1.52
  text "1.300mm (51.18mil)" at 248.124,105.913 h1.52
  text "PTH" at 264.291,105.913 h1.52
  text "Round" at 270.875,105.913 h1.52
  text "Top Copper - Bottom Copper" at 280.406,105.913 h1.52
  text "11" at 239.687,102.75 h1.52
  text "1.700mm (66.93mil)" at 248.124,102.75 h1.52
  text "PTH" at 264.291,102.75 h1.52
  text "Round" at 270.875,102.75 h1.52
  text "Top Copper - Bottom Copper" at 280.406,102.75 h1.52
  text "B" at 231.407,102.497 h1.41
  text "22" at 239.687,99.588 h1.52
  text "2.000mm (78.74mil)" at 248.124,99.588 h1.52
  text "PTH" at 264.291,99.588 h1.52
  text "Round" at 270.875,99.588 h1.52
  text "Top Copper - Bottom Copper" at 280.406,99.588 h1.52
  text "A" at 231.407,99.334 h1.41
  text "20" at 239.687,96.426 h1.52
  text "2.540mm (100.00mil)" at 248.124,96.426 h1.52
  text "PTH" at 264.291,96.426 h1.52
  text "Round" at 270.875,96.426 h1.52
  text "Top Copper - Bottom Copper" at 280.406,96.426 h1.52
  text "9" at 239.687,93.263 h1.52
  text "4.500mm (177.17mil)" at 248.124,93.263 h1.52
  text "PTH" at 264.291,93.263 h1.52
  text "Round" at 270.875,93.263 h1.52
  text "Top Copper - Bottom Copper" at 280.406,93.263 h1.52
  text "G" at 231.407,93.01 h1.41
  text "2349 Total" at 239.687,90.101 h1.52
  text ".Layer_Name" at 14.656,-21.806 h1.52
Hole Dims:
  circle w0.254: c4,4 r2.25
  circle w0.254: c4,81 r2.25
  circle w0.254: c120,70 r2.25
  circle w0.254: c120,4 r2.25
  circle w0.254: c212.25,41 r2.25
  circle w0.254: c300,70 r2.25
  circle w0.254: c300,4 r2.25
  circle w0.254: c396,4 r2.25
  circle w0.254: c396,81 r2.25
  lines w0.2: 180,0 180,85 ; 240,0 240,85

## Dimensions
0,-0.5 to 400,-0.5 on M16 Courtyards Bottom
-0.5,0 to -0.5,85 on M16 Courtyards Bottom
180,-0.548 to 240,-0.5 on M16 Courtyards Bottom
0,-0.5 to 180,-0.5 on M16 Courtyards Bottom
80,135.5 to 0,135.5 on M2 Board Dimensions
400.5,0 to 400.5,85 on M2 Board Dimensions
0,-0.5 to 400,-0.5 on M2 Board Dimensions
-0.5,0 to -0.5,135 on M2 Board Dimensions
4,78.25 to 0,84 on M16 Courtyards Bottom
-0.024,73.992 to 120,67 on M16 Courtyards Bottom
400,85.5 to 396,85.5 on M16 Courtyards Bottom
300,67 to 400.024,74 on M16 Courtyards Bottom
0,0 to 212.25,44 on M16 Courtyards Bottom
393.25,4 to 393.25,0 on M16 Courtyards Bottom
393.25,85 to 393.25,81 on M16 Courtyards Bottom
400,85 to 297.25,70 on M16 Courtyards Bottom
215,41 to 0,0 on M16 Courtyards Bottom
